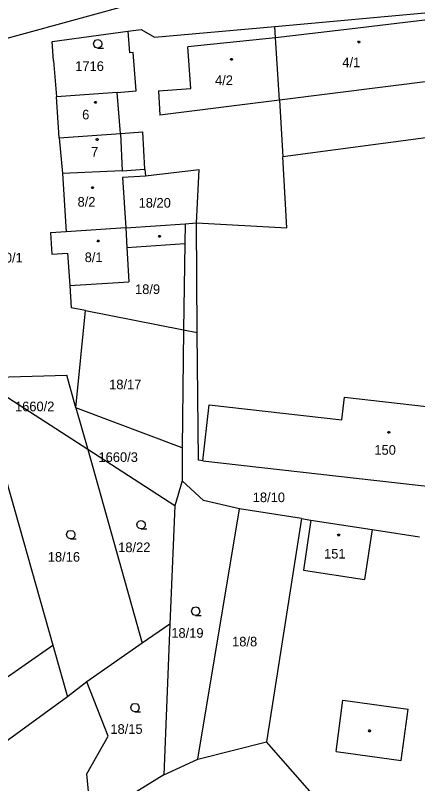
# Model space of a CAD drawing. Extents: x -802857 to -799647, y -1020285 to -1015884.
# Drawn here: x -801393.5 to -801322.5, y -1017775.9 to -1017640.2 of the extents above; entities that cross this region are included whole.
import ezdxf

# ---------------------------------------------------------------- set-up
doc = ezdxf.new("R2010")
doc.units = 0
for name, color, linetype in [('Default', 7, 'Continuous'), ('KN_HRANICE', 7, 'Continuous'), ('KN_KULTURY', 7, 'Continuous'), ('KN_PARCELY', 7, 'Continuous'), ('KN_SLUCKY', 7, 'Continuous')]:
    doc.layers.add(name, color=color, linetype=linetype)

# ---------------------------------------------------------------- blocks, each defined once
blk = doc.blocks.new('304')
at = {"layer": 'Default'}
blk.add_lwpolyline([(0, 0), (-0.38, 0.1), (-0.65, 0.37), (-0.75, 0.74), (-0.65, 1.11), (-0.38, 1.38), (-0.01, 1.48), (0.36, 1.38), (0.63, 1.11), (0.73, 0.73), (0.63, 0.35), (0.36, 0.08), (-0.02, -0.02), (0.98, -0.02)], dxfattribs=at)
blk = doc.blocks.new('NAHRADNI_SYMBOL')
at = {"layer": 'Default'}
blk.add_lwpolyline([(0.09, 0.15), (0.18, 0), (0.09, -0.15), (-0.09, -0.15), (-0.18, 0), (-0.09, 0.15), (0.09, 0.15)], dxfattribs=at)
blk = doc.blocks.new('402')
at = {"layer": 'Default'}
blk.add_lwpolyline([(0.09, 0.15), (0.18, 0), (0.09, -0.15), (-0.09, -0.15), (-0.18, 0), (-0.09, 0.15), (0.09, 0.15)], dxfattribs=at)

msp = doc.modelspace()

# ---------------------------------------------------------------- linework, layer by layer
at = {"layer": 'KN_HRANICE'}
for p, q in [((-801436.88, -1017655.78), (-801344.28, -1017630.37)), ((-801347.72, -1017642.2), (-801317.19, -1017639.44)), ((-801387, -1017644.83), (-801373.65, -1017643.04)), ((-801373.65, -1017643.04), (-801371.28, -1017642.72)), ((-801373.65, -1017643.04), (-801373.36, -1017646.87)), ((-801371.28, -1017642.72), (-801368.91, -1017644.12)), ((-801368.91, -1017644.12), (-801347.72, -1017642.2)), ((-801347.58, -1017644.22), (-801347.72, -1017642.2)), ((-801346.88, -1017655.22), (-801347.58, -1017644.22)), ((-801386.74, -1017648.25), (-801387, -1017644.83)), ((-801372.67, -1017646.8), (-801373.36, -1017646.87)), ((-801372.17, -1017653.55), (-801372.67, -1017646.8)), ((-801386.74, -1017648.25), (-801386.24, -1017654.63)), ((-801375.49, -1017653.85), (-801386.24, -1017654.63)), ((-801375.49, -1017653.85), (-801372.17, -1017653.55)), ((-801374.94, -1017661.08), (-801375.49, -1017653.85)), ((-801385.72, -1017661.85), (-801386.24, -1017654.63)), ((-801346.88, -1017655.22), (-801346.31, -1017665.23)), ((-801374.94, -1017661.08), (-801371.01, -1017660.78)), ((-801370.64, -1017667.41), (-801371.01, -1017660.78)), ((-801385.72, -1017661.85), (-801374.94, -1017661.08)), ((-801385.72, -1017661.85), (-801385.15, -1017668.16)), ((-801314.72, -1017661.03), (-801346.31, -1017665.23)), ((-801345.56, -1017677.77), (-801346.31, -1017665.23)), ((-801374.65, -1017667.67), (-801370.64, -1017667.41)), ((-801370.64, -1017667.41), (-801370.54, -1017668.61)), ((-801361.03, -1017667.51), (-801370.54, -1017668.61)), ((-801361.54, -1017676.89), (-801361.03, -1017667.51)), ((-801374.65, -1017667.67), (-801385.15, -1017668.16)), ((-801385.15, -1017668.16), (-801384.5, -1017678.44)), ((-801370.54, -1017668.61), (-801374.57, -1017668.87)), ((-801374.57, -1017668.87), (-801374.01, -1017677.75)), ((-801374.01, -1017677.75), (-801363.53, -1017677.06)), ((-801363.53, -1017677.06), (-801361.54, -1017676.89)), ((-801361.37, -1017696.22), (-801361.54, -1017676.89)), ((-801361.54, -1017676.89), (-801345.56, -1017677.77)), ((-801384.5, -1017678.44), (-801387.29, -1017678.62)), ((-801374.01, -1017677.75), (-801384.5, -1017678.44)), ((-801387.29, -1017678.62), (-801387.04, -1017682.41)), ((-801373.8, -1017681.22), (-801363.58, -1017680.51)), ((-801363.58, -1017680.51), (-801363.78, -1017695.75)), ((-801387.04, -1017682.41), (-801384.25, -1017682.23)), ((-801384.25, -1017682.23), (-801383.87, -1017687.92)), ((-801373.8, -1017681.22), (-801373.44, -1017687.26)), ((-801383.87, -1017687.92), (-801373.44, -1017687.26)), ((-801383.87, -1017687.92), (-801383.61, -1017691.85)), ((-801381.12, -1017692.34), (-801383.61, -1017691.85)), ((-801382.78, -1017709.52), (-801381.12, -1017692.34)), ((-801381.12, -1017692.34), (-801363.78, -1017695.75)), ((-801363.78, -1017695.75), (-801364.05, -1017716.58)), ((-801363.78, -1017695.75), (-801361.37, -1017696.22)), ((-801361.18, -1017718.78), (-801361.37, -1017696.22)), ((-801400.33, -1017704.19), (-801384.4, -1017703.77)), ((-801400.33, -1017704.19), (-801386.84, -1017751.44)), ((-801380.71, -1017716.88), (-801400.33, -1017704.19)), ((-801382.78, -1017709.52), (-801384.4, -1017703.77)), ((-801364.05, -1017716.58), (-801382.78, -1017709.52)), ((-801382.78, -1017709.52), (-801380.71, -1017716.88)), ((-801365.33, -1017726.83), (-801380.71, -1017716.88)), ((-801380.71, -1017716.88), (-801371.09, -1017751.09)), ((-801364.05, -1017716.58), (-801364.06, -1017722.39)), ((-801360.4, -1017718.86), (-801361.18, -1017718.78)), ((-801360.4, -1017718.86), (-801315.22, -1017724.02)), ((-801364.06, -1017722.39), (-801365.33, -1017726.83)), ((-801360.25, -1017725.9), (-801364.06, -1017722.39)), ((-801353.93, -1017727.34), (-801360.25, -1017725.9)), ((-801365.33, -1017726.83), (-801366.23, -1017747.72)), ((-801361.29, -1017771.58), (-801353.93, -1017727.34)), ((-801342.99, -1017729.09), (-801353.93, -1017727.34)), ((-801342.99, -1017729.09), (-801349.19, -1017768.52)), ((-801342.99, -1017729.09), (-801341.32, -1017729.38)), ((-801341.32, -1017729.38), (-801330.53, -1017731.02)), ((-801330.53, -1017731.02), (-801322.14, -1017732.32)), ((-801366.23, -1017747.72), (-801371.09, -1017751.09)), ((-801366.23, -1017747.72), (-801367.27, -1017774.31)), ((-801386.84, -1017751.44), (-801384.3, -1017760.57)), ((-801371.09, -1017751.09), (-801380.85, -1017757.91)), ((-801380.85, -1017757.91), (-801384.3, -1017760.57)), ((-801377.08, -1017767.48), (-801380.85, -1017757.91)), ((-801384.3, -1017760.57), (-801402.96, -1017774.15)), ((-801380.85, -1017774.15), (-801377.08, -1017767.48)), ((-801361.29, -1017771.58), (-801349.19, -1017768.52)), ((-801338.75, -1017780.31), (-801349.19, -1017768.52)), ((-801367.27, -1017774.31), (-801361.29, -1017771.58)), ((-801380.06, -1017782.2), (-801380.85, -1017774.15)), ((-801367.27, -1017774.31), (-801380.06, -1017782.2))]:
    msp.add_line(p, q, dxfattribs=at)
at = {"layer": 'KN_SLUCKY'}
for p, q in [((-801317.18, -1017640.62), (-801334.53, -1017642.7)), ((-801334.53, -1017642.7), (-801347.58, -1017644.22)), ((-801347.58, -1017644.22), (-801363.02, -1017645.81)), ((-801362.49, -1017653.14), (-801363.02, -1017645.81)), ((-801315.88, -1017651.33), (-801346.88, -1017655.22)), ((-801368.2, -1017653.58), (-801362.49, -1017653.14)), ((-801368.2, -1017653.58), (-801367.99, -1017657.86)), ((-801346.88, -1017655.22), (-801367.99, -1017657.86)), ((-801374.94, -1017661.08), (-801374.65, -1017667.67)), ((-801363.53, -1017677.06), (-801363.58, -1017680.51)), ((-801374.01, -1017677.75), (-801373.8, -1017681.22)), ((-801335.87, -1017711.65), (-801335.42, -1017707.67)), ((-801335.42, -1017707.67), (-801320.96, -1017709.32)), ((-801360.4, -1017718.86), (-801359.27, -1017708.97)), ((-801359.27, -1017708.97), (-801335.87, -1017711.65)), ((-801341.32, -1017729.38), (-801342.64, -1017738.21)), ((-801330.53, -1017731.02), (-801331.85, -1017739.85)), ((-801342.64, -1017738.21), (-801331.85, -1017739.85)), ((-801408.92, -1017766.74), (-801386.84, -1017751.44)), ((-801336.9, -1017770.22), (-801335.67, -1017761.12)), ((-801335.67, -1017761.12), (-801324.19, -1017762.71)), ((-801325.42, -1017771.81), (-801324.19, -1017762.71)), ((-801336.9, -1017770.22), (-801325.42, -1017771.81))]:
    msp.add_line(p, q, dxfattribs=at)

# ---------------------------------------------------------------- block references
at = {"layer": 'KN_KULTURY'}
for name, p in [('304', (-801378.93, -1017646.01)), ('402', (-801332.86, -1017644.95)), ('402', (-801355.34, -1017648.02)), ('NAHRADNI_SYMBOL', (-801379.35, -1017655.58)), ('402', (-801379.04, -1017662.16)), ('402', (-801379.85, -1017670.67)), ('402', (-801368.03, -1017679.26)), ('402', (-801378.85, -1017680.06)), ('402', (-801327.58, -1017713.87)), ('304', (-801371.28, -1017730.89)), ('304', (-801383.7, -1017732.65)), ('402', (-801336.43, -1017731.99)), ('304', (-801361.65, -1017746.16)), ('304', (-801372.36, -1017763.19)), ('402', (-801330.98, -1017766.55))]:
    msp.add_blockref(name, p, dxfattribs=at)

# ---------------------------------------------------------------- texts
at = {"layer": 'KN_PARCELY'}
for s, p in [('1716', (-801382.91, -1017650.05)), ('4/1', (-801335.79, -1017649.39)), ('4/2', (-801358.24, -1017652.55)), ('6', (-801381.69, -1017658.61)), ('7', (-801380.1, -1017665.17)), ('8/2', (-801382.5, -1017674.01)), ('18/20', (-801371.73, -1017674.18)), ('1660/1', (-801399.13, -1017683.87)), ('8/1', (-801381.24, -1017683.8)), ('18/9', (-801372.36, -1017689.44)), ('18/17', (-801376.93, -1017706.25)), ('1660/2', (-801393.54, -1017710.13)), ('150', (-801330.13, -1017717.81)), ('1660/3', (-801378.81, -1017719.08)), ('18/10', (-801351.59, -1017726.18)), ('18/22', (-801375.33, -1017735)), ('18/16', (-801387.75, -1017736.69)), ('151', (-801339.01, -1017736.13)), ('18/19', (-801365.96, -1017750.12)), ('18/8', (-801355.23, -1017751.64)), ('18/15', (-801376.71, -1017767.08))]:
    msp.add_text(s, height=1.7, dxfattribs=at).set_placement(p)

doc.saveas('drawing.dxf')
